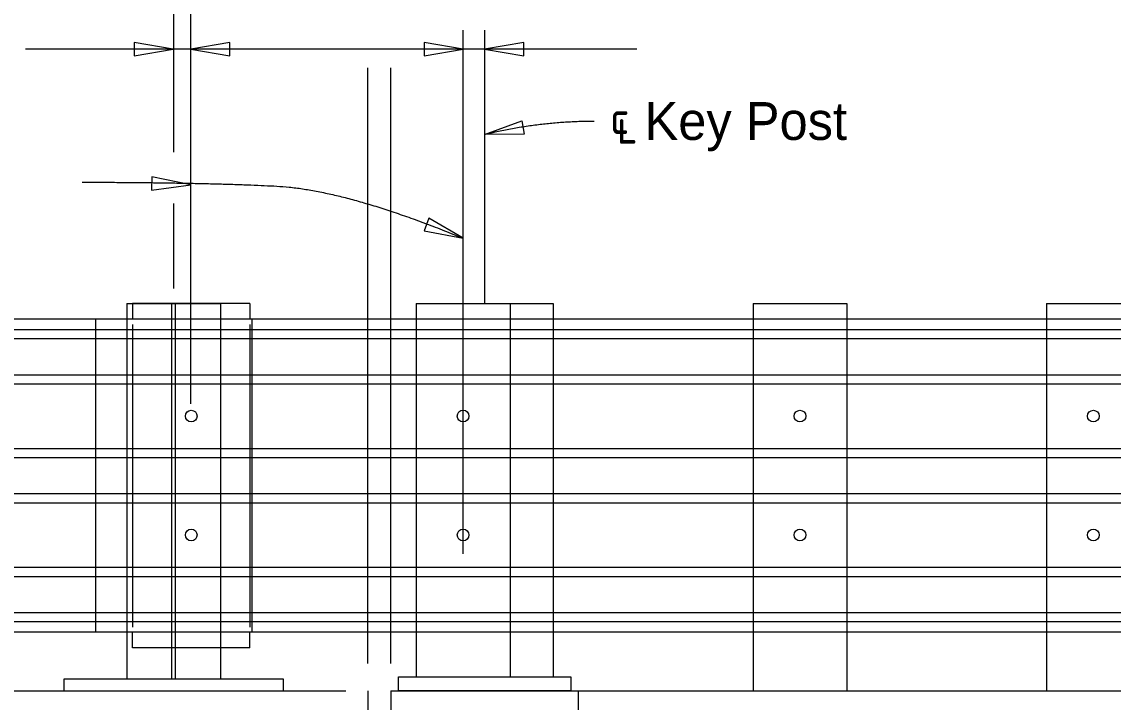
# Model space of a CAD drawing. Extents: x 21665 to 21741.5, y 56121.9 to 56164.2.
# Drawn here: x 21682.72 to 21688.53, y 56142.36 to 56145.98 of the extents above; entities that cross this region are included whole.
import ezdxf

# ---------------------------------------------------------------- set-up
doc = ezdxf.new("R2010")
doc.units = 0
for name, color, linetype in [('Dimension', 7, 'Continuous'), ('ExistSuperStruct', 7, 'Continuous'), ('Miscellaneous', 7, 'Continuous'), ('SteelMisc', 7, 'Continuous'), ('SteelMisc_h', 7, 'Continuous'), ('StrMiscConc', 7, 'Continuous'), ('TextStructures', 7, 'Continuous')]:
    doc.layers.add(name, color=color, linetype=linetype)

msp = doc.modelspace()

# ---------------------------------------------------------------- linework, layer by layer
at = {"layer": 'Dimension'}
for p, q in [((21685.993, 56145.8354), (21682.7355, 56145.8354)), ((21684.5591, 56142.5641), (21684.5591, 56145.7363)), ((21684.6816, 56142.5641), (21684.6816, 56145.7363))]:
    msp.add_line(p, q, dxfattribs=at)
for points in [[(21683.5229, 56145.8354), (21683.3147, 56145.8706), (21683.3147, 56145.8001)], [(21683.6167, 56145.8354), (21683.8249, 56145.8001), (21683.8249, 56145.8706)], [(21685.0671, 56145.8354), (21684.8588, 56145.8706), (21684.8588, 56145.8001)], [(21685.1816, 56145.8354), (21685.3899, 56145.8001), (21685.3899, 56145.8706)], [(21685.1817, 56145.3808), (21685.3804, 56145.4526), (21685.3929, 56145.3831)], [(21683.6167, 56145.1122), (21683.4099, 56145.1552), (21683.4073, 56145.0847)], [(21685.0671, 56144.8279), (21684.8845, 56144.9341), (21684.8597, 56144.868)]]:
    msp.add_lwpolyline(points, close=True, dxfattribs=at)
for points in [[(21685.1816, 56145.3812), (21685.4732, 56145.452), (21685.7647, 56145.452)], [(21683.0388, 56145.1264), (21683.7111, 56145.1251), (21684.4414, 56145.0855), (21685.0671, 56144.8279)]]:
    msp.add_open_spline(points, degree=2, dxfattribs=at)
at = {"layer": 'ExistSuperStruct'}
for p, q in [((21674.8449, 56142.4186), (21684.442, 56142.4186)), ((21684.5592, 56142.4187), (21684.5592, 56141.002)), ((21684.6816, 56142.4187), (21685.6816, 56142.4187)), ((21684.6817, 56142.4187), (21684.6817, 56139.814))]:
    msp.add_line(p, q, dxfattribs=at)
at = {"layer": 'Miscellaneous'}
for p, q in [((21683.6167, 56143.9469), (21683.6167, 56147.9653)), ((21683.5254, 56146.933), (21683.5254, 56145.2866)), ((21685.0671, 56143.1469), (21685.0671, 56145.9361)), ((21685.1816, 56145.9361), (21685.1816, 56144.4812)), ((21683.5254, 56145.0138), (21683.5254, 56144.5595)), ((21683.9316, 56144.4811), (21683.3066, 56144.4811)), ((21683.3066, 56144.4811), (21683.3066, 56144.3977)), ((21683.9316, 56144.4811), (21683.9316, 56144.3977)), ((21684.817, 56144.4812), (21685.5462, 56144.4812)), ((21684.817, 56144.4812), (21684.817, 56142.4916)), ((21685.317, 56144.4812), (21685.317, 56142.4916)), ((21686.6112, 56144.4811), (21686.6112, 56142.4186)), ((21686.6112, 56144.4811), (21687.1112, 56144.4811)), ((21687.1112, 56144.4811), (21687.1112, 56142.4186)), ((21688.1737, 56144.4811), (21688.1737, 56142.4186)), ((21688.1737, 56144.4811), (21688.6737, 56144.4811)), ((21683.1087, 56144.3977), (21683.1087, 56142.7311)), ((21683.3066, 56144.3692), (21683.3066, 56142.7573)), ((21683.9316, 56144.3692), (21683.9316, 56142.7573)), ((21683.942, 56144.3977), (21683.942, 56142.7311)), ((21683.1087, 56144.3422), (21692.4071, 56144.3422)), ((21683.1087, 56144.294), (21692.4071, 56144.294)), ((21683.1087, 56144.1012), (21692.4071, 56144.1012)), ((21683.1087, 56144.053), (21692.4071, 56144.053)), ((21683.1087, 56143.709), (21692.4071, 56143.709)), ((21683.1087, 56143.6608), (21692.4071, 56143.6608)), ((21683.1087, 56143.468), (21692.4071, 56143.468)), ((21683.1087, 56143.4198), (21692.4071, 56143.4198)), ((21683.1087, 56143.0759), (21692.4071, 56143.0759)), ((21683.1087, 56143.0276), (21692.4071, 56143.0276)), ((21683.1087, 56142.8348), (21692.4071, 56142.8348)), ((21683.1087, 56142.7866), (21692.4071, 56142.7866)), ((21683.3066, 56142.6477), (21683.3066, 56142.7311)), ((21683.9316, 56142.6477), (21683.9316, 56142.7311)), ((21683.9316, 56142.6477), (21683.3066, 56142.6477))]:
    msp.add_line(p, q, dxfattribs=at)
for centre in [(21685.067, 56143.8811), (21685.067, 56143.2479)]:
    msp.add_circle(centre, 0.0312, dxfattribs=at)
at = {"layer": 'SteelMisc'}
for p, q in [((21683.2754, 56144.4811), (21683.7754, 56144.4811)), ((21683.2754, 56144.4811), (21683.2754, 56144.3977)), ((21683.7754, 56144.4811), (21683.7754, 56144.3977)), ((21683.1087, 56144.3977), (21674.8449, 56144.3977)), ((21674.8449, 56144.3422), (21683.1087, 56144.3422)), ((21674.8449, 56144.294), (21683.1087, 56144.294)), ((21674.8449, 56144.1012), (21683.1087, 56144.1012)), ((21674.8449, 56144.053), (21683.1087, 56144.053)), ((21674.8449, 56143.709), (21683.1087, 56143.709)), ((21674.8449, 56143.6608), (21683.1087, 56143.6608)), ((21674.8449, 56143.468), (21683.1087, 56143.468)), ((21674.8449, 56143.4198), (21683.1087, 56143.4198)), ((21674.8449, 56143.0759), (21683.1087, 56143.0759)), ((21674.8449, 56143.0276), (21683.1087, 56143.0276)), ((21674.8449, 56142.8348), (21683.1087, 56142.8348)), ((21674.8449, 56142.7866), (21683.1087, 56142.7866)), ((21683.1087, 56142.7311), (21674.8449, 56142.7311)), ((21683.2754, 56142.7311), (21683.2754, 56142.4811)), ((21683.7754, 56142.7311), (21683.7754, 56142.4811)), ((21682.942, 56142.4811), (21684.1087, 56142.4811)), ((21682.942, 56142.4186), (21682.942, 56142.4811)), ((21683.2754, 56142.4811), (21683.7754, 56142.4811)), ((21684.1087, 56142.4811), (21684.1087, 56142.4186)), ((21682.942, 56142.4186), (21684.1087, 56142.4186))]:
    msp.add_line(p, q, dxfattribs=at)
for centre in [(21683.6191, 56143.881), (21683.6191, 56143.2479)]:
    msp.add_circle(centre, 0.0312, dxfattribs=at)
at = {"layer": 'SteelMisc_h'}
for p, q in [((21683.515, 56142.4811), (21683.515, 56144.4811)), ((21683.5358, 56142.4811), (21683.5358, 56144.4811)), ((21684.9629, 56144.4812), (21685.0462, 56144.4812)), ((21685.5462, 56144.4812), (21685.5462, 56142.4916)), ((21692.4071, 56144.3977), (21683.1087, 56144.3977)), ((21683.2754, 56144.3977), (21683.2754, 56142.7311)), ((21683.7754, 56144.3977), (21683.7754, 56142.7311)), ((21692.4071, 56142.7311), (21683.1087, 56142.7311))]:
    msp.add_line(p, q, dxfattribs=at)
msp.add_lwpolyline([(21684.7233, 56142.4187), (21684.7233, 56142.4916), (21685.64, 56142.4916), (21685.64, 56142.4187)], close=True, dxfattribs=at)
for centre in [(21686.8612, 56143.881), (21688.4237, 56143.881), (21686.8612, 56143.2479), (21688.4237, 56143.2479)]:
    msp.add_circle(centre, 0.0312, dxfattribs=at)
at = {"layer": 'StrMiscConc'}
for p, q in [((21685.6816, 56142.4187), (21688.6816, 56142.4187)), ((21685.6816, 56141.6687), (21685.6816, 56142.4187))]:
    msp.add_line(p, q, dxfattribs=at)

# ---------------------------------------------------------------- texts
at = {"layer": 'TextStructures'}
msp.add_text('℄ Key Post', height=0.2016, dxfattribs=at).set_placement((21685.8489, 56145.3516))

doc.saveas('drawing.dxf')
